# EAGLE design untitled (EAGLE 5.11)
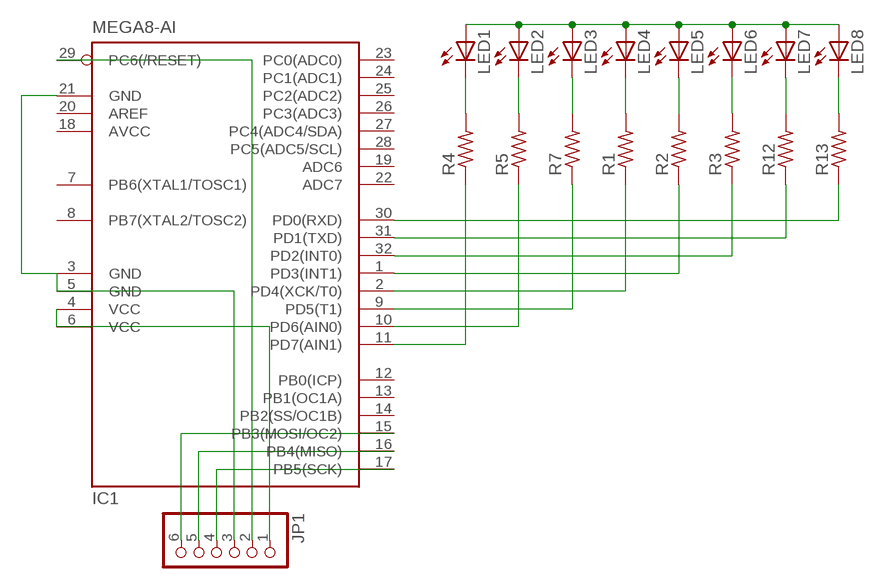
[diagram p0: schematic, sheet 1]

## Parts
IC1  MEGA8-AI  [TQFP32-08]
JP1  PINHD-1X6  [1X06]
LED1  LED3MM  [LED3MM]
LED2  LED3MM  [LED3MM]
LED3  LED3MM  [LED3MM]
LED4  LED3MM  [LED3MM]
LED5  LED3MM  [LED3MM]
LED6  LED3MM  [LED3MM]
LED7  LED3MM  [LED3MM]
LED8  LED3MM  [LED3MM]
R1  R-US_0207/2V  [0207/2V]
R2  R-US_0207/2V  [0207/2V]
R3  R-US_0207/2V  [0207/2V]
R4  R-US_0207/5V  [0207/5V]
R5  R-US_0207/5V  [0207/5V]
R7  R-US_0207/2V  [0207/2V]
R12  R-US_0207/2V  [0207/2V]
R13  R-US_0207/2V  [0207/2V]

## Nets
N$1: LED1.A LED2.A LED3.A LED4.A LED5.A LED6.A LED7.A LED8.A
N$2: IC1.11(PD7(AIN1)) R4.1
N$3: IC1.10(PD6(AIN0)) R5.1
N$4: IC1.9(PD5(T1)) R7.1
N$5: IC1.2(PD4(XCK/T0)) R1.1
N$6: IC1.1(PD3(INT1)) R2.1
N$7: IC1.32(PD2(INT0)) R3.1
N$8: IC1.31(PD1(TXD)) R12.1
N$9: IC1.30(PD0(RXD)) R13.1
N$14: IC1.15(PB3(MOSI/OC2)) JP1.6
N$15: IC1.16(PB4(MISO)) JP1.5
N$16: IC1.17(PB5(SCK)) JP1.4
N$17: IC1.29(PC6(/RESET)) JP1.2
N$18: IC1.4(VCC) IC1.6(VCC) JP1.1
N$22: IC1.3(GND) IC1.5(GND) IC1.21(GND) JP1.3
N$25: LED8.K(C) R13.2
N$28: LED7.K(C) R12.2
N$39: LED6.K(C) R3.2
N$40: LED5.K(C) R2.2
N$41: LED4.K(C) R1.2
N$42: LED3.K(C) R7.2
N$43: LED2.K(C) R5.2
N$44: LED1.K(C) R4.2
Unconnected: IC1.7(PB6(XTAL1/TOSC1)) IC1.8(PB7(XTAL2/TOSC2)) IC1.12(PB0(ICP)) IC1.13(PB1(OC1A)) IC1.14(PB2(SS/OC1B)) IC1.19(ADC6) IC1.20(AREF) IC1.22(ADC7) IC1.23(PC0(ADC0)) IC1.24(PC1(ADC1)) IC1.25(PC2(ADC2)) IC1.26(PC3(ADC3)) IC1.27(PC4(ADC4/SDA)) IC1.28(PC5(ADC5/SCL))

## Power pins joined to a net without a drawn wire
AVCC: IC1.18(AVCC)

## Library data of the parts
IC1 = atmel:MEGA8: MICROCONTROLLER 8 Kbytes FLASH, 1 kbytes SRAM, 512 bytes EEPROM, USART, 6-channel 10 bit ADC, 2-channel 8 bit ADC Pin compatible with Atmega48, ATMega88, ATMega168 Source: avr.lbr; MPN: ATMEGA8-16AU; OC_FARNELL: 9171371; OC_NEWARK: 73M8863
JP1 = pinhead:PINHD-1X6: PIN HEADER
LED1-LED8 = led:LED: LED
R1-R5 R7 R12 R13 = rcl:R-US_: RESISTOR, American symbol

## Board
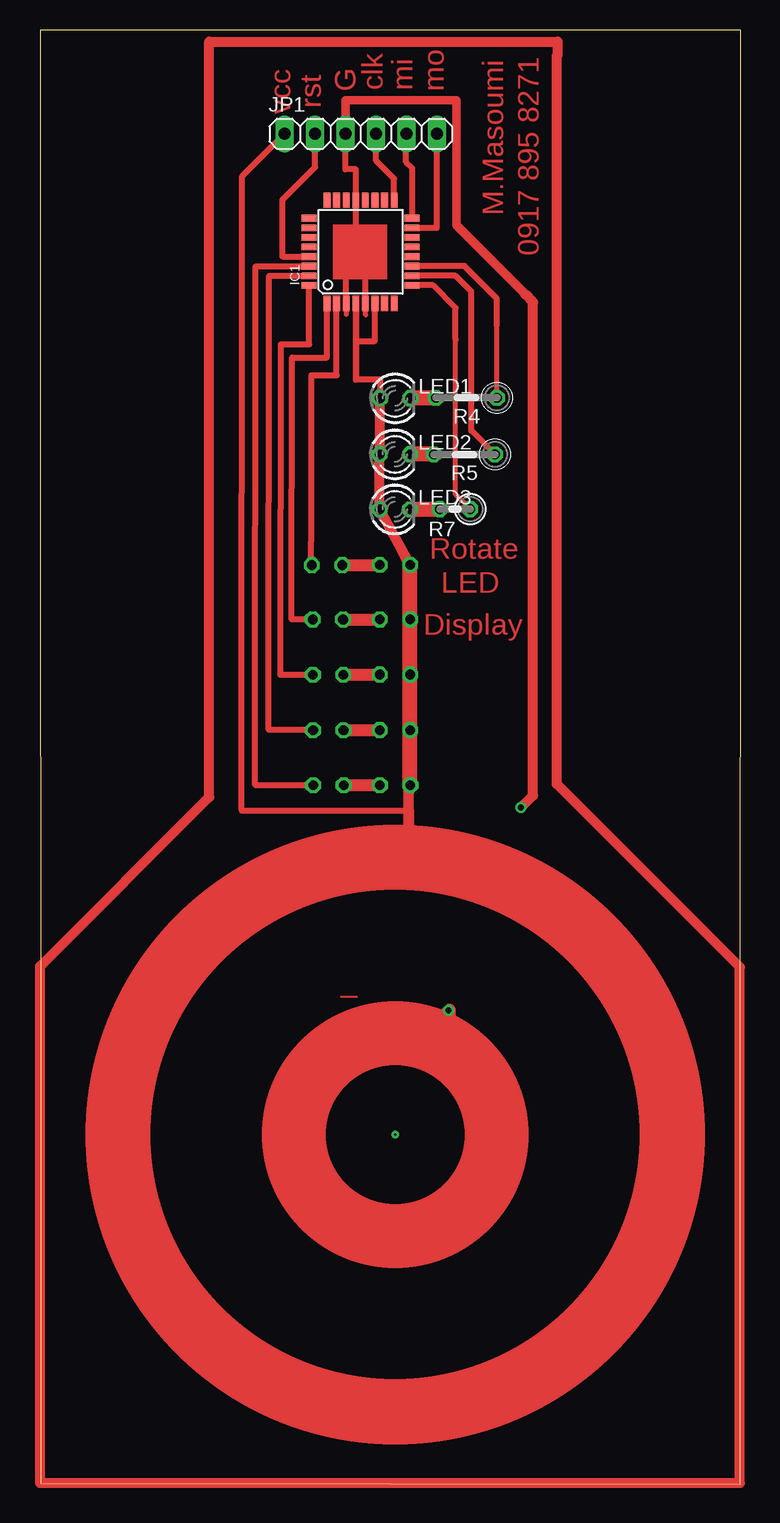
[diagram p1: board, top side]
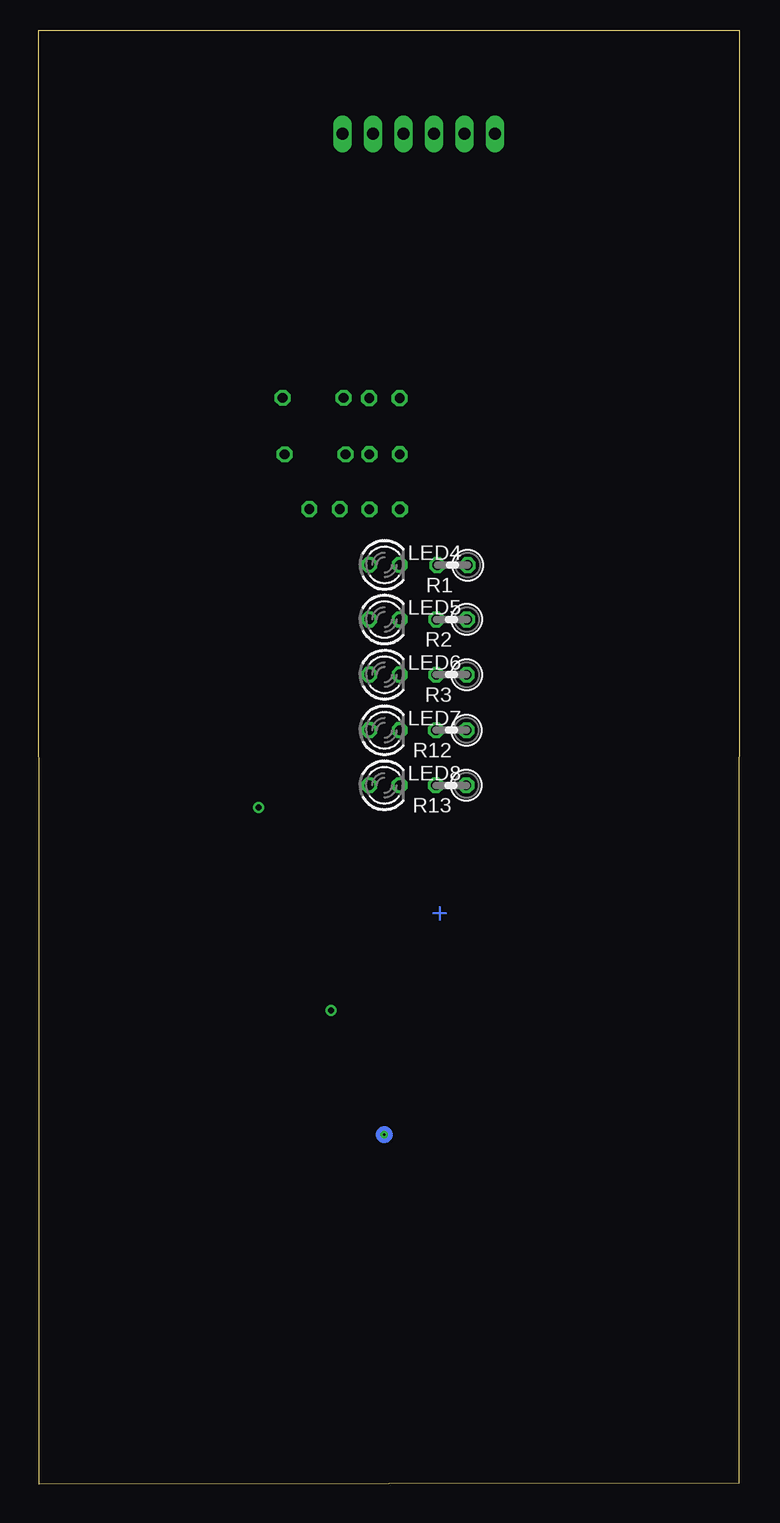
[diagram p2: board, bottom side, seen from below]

Size 58.41 x 121.22 mm. Coordinates in mm from the lower left corner, seen from the top.
Outline: 0.05,0.07 58.39,0 58.41,121.18 0,121.22 0.05,0.07
Copper layers (1*16): Top 0.035mm / dielectric 1.5mm / Bottom 0.035mm
Design rules "default": minimum track width 10mil, minimum drill 24mil, track to track 8mil, track to pad 8mil, pad to pad 8mil, via to via 8mil, smd to smd 8mil, copper to edge 40mil, drill to drill 8mil, minimum pad ring 10mil, minimum via ring 8mil, stop-mask expansion 4mil, vias tented up to drill 0mil, thermal gap 10mil

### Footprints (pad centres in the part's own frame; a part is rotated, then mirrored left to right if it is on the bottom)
TQFP32-08 = smd 1.27 x 0.559: 1 -4.293,2.8; 2 -4.293,2; 3 -4.293,1.2; 4 -4.293,0.4; 5 -4.293,-0.4; 6 -4.293,-1.2; 7 -4.293,-2; 8 -4.293,-2.8; 17 4.293,-2.8; 18 4.293,-2; 19 4.293,-1.2; 20 4.293,-0.4; 21 4.293,0.4; 22 4.293,1.2; 23 4.293,2; 24 4.293,2.8 | smd 0.559 x 1.27: 9 -2.8,-4.293; 10 -2,-4.293; 11 -1.2,-4.293; 12 -0.4,-4.293; 13 0.4,-4.293; 14 1.2,-4.293; 15 2,-4.293; 16 2.8,-4.293; 25 2.8,4.293; 26 2,4.293; 27 1.2,4.293; 28 0.4,4.293; 29 -0.4,4.293; 30 -1.2,4.293; 31 -2,4.293; 32 -2.8,4.293
1X06 = drill 1.016 long: 1 -6.35,0; 2 -3.81,0; 3 -1.27,0; 4 1.27,0; 5 3.81,0; 6 6.35,0
LED3MM = drill 0.813 octagon: A -1.27,0; K 1.27,0
0207/2V = drill 0.813 octagon: 1 -1.27,0; 2 1.27,0
0207/5V = drill 0.813 octagon: 1 -2.54,0; 2 2.54,0

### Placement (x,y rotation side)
IC1  26.73,102.73 90 top
JP1  26.74,112.57 0 top
LED1  29.61,90.53 0 top
LED2  29.59,85.86 0 top
LED3  29.59,81.27 0 top
LED4  29.59,76.64 0 bottom
LED5  29.6,72.09 0 bottom
LED6  29.6,67.49 0 bottom
LED7  29.6,62.86 0 bottom
LED8  29.6,58.27 0 bottom
R1  23.93,76.61 180 bottom
R2  24,72.09 180 bottom
R3  24.02,67.48 180 bottom
R4  35.55,90.56 180 top
R5  35.38,85.85 180 top
R7  34.6,81.29 180 top
R12  24.03,62.85 180 bottom
R13  24.05,58.26 180 bottom

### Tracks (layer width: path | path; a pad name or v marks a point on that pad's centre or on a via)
N$1
  Top 0.813: LED1.A 28.34,85.87 LED2.A LED3.A LED4.A
  Top 1.27: LED8.A LED7.A | LED7.A | LED7.A LED6.A LED5.A LED4.A
N$2
  Top 0.406: R4.1 38.09,96.6
  Top 0.483: IC1.11 35.39,101.54 38.09,98.84 38.09,96.6
N$3
  Top 0.483: IC1.10 34.64,100.73 35.96,99.42 35.96,95.9 35.96,95.49 35.96,87.81 R5.1
N$4
  Top 0.406: R7.1 34.66,82.5 34.66,95.44
  Top 0.483: IC1.9 31.03,99.94 32.76,99.94 34.66,98.05 34.66,95.44
N$5
  Top 0.483: R1.1 22.62,76.61 22.62,78.63 22.62,92.45 24.73,92.45 IC1.2
N$6
  Top 0.483: IC1.1 23.93,93.93 21.03,93.93 20.99,72.09 R2.1
N$7
  Top 0.483: IC1.32 22.44,95.02 20.09,95.02 20.05,67.48 R3.1
N$8
  Top 0.483: IC1.31 19.1,100.73 19.06,62.89 22.76,62.89 R12.1
N$9
  Top 0.483: IC1.30 17.98,101.53 17.93,58.29 22.78,58.29 R13.1
N$11
  Top 0.813: 30.73,54.23 30.73,58.88 31,58.88
N$12
  Top 0.813: 0.01,0.13 0.01,43.17 14.11,57.27 14.11,120.25 43.16,120.25 43.16,119.14 43.11,119.14
N$13  (via drill 0.23 pad 0.25)
  other vias: 29.61,29.15
N$14
  Top 0.483: JP1.6 33.09,104.73 IC1.15
N$15
  Top 0.483: IC1.16 31.05,105.53 31.05,109.69 30.52,110.22 30.52,112.53 JP1.5
N$16
  Top 0.483: IC1.17 29.53,108.82 28.02,110.33 JP1.4
N$17
  Top 0.483: IC1.29 20.2,102.33 20.2,107.07 22.93,109.8 JP1.2
N$18
  Top 0.483: IC1.6 27.93,95.3 26.33,95.3 | 26.33,95.3 IC1.4 26.33,92.08 | JP1.1 16.86,109.04 16.82,56.15 16.82,56.16 30.95,56.16 | 30.95,56.16 30.95,54.38 30.67,54.38 | 30.95,56.16 30.95,59.08 30.87,75.98 28.44,80.93 28.24,89.3 28.37,89.3 28.37,92.06 26.33,92.06 26.33,95.3
N$19
  Top 0.813: -0.03,0.1 58.35,0.1 58.35,43.12 43.1,58.37 43.1,119.07
N$22
  Top 0.483: IC1.3 25.53,102.09 26.33,102.09 | IC1.5 27.1,98.44 27.1,102.09 26.33,102.09 | 26.33,102.09 IC1.21 26.33,109.61 25.46,109.61 25.46,112.57 JP1.3
N$24
  Top 0.713: 25.48,111.88 25.48,115.37 34.7,115.37 34.7,104.94 40.45,99.19 | 40.11,56.39 40.45,56.73
  Top 0.813: 40.45,99.19 41.12,98.52 41.12,57.39 40.11,56.39
N$25
  Top 1.016: LED8.K 25.33,58.27 R13.2
N$28
  Top 1.016: R12.2 LED7.K
N$29  (via drill 0.5 pad 0.18)
  other vias: 40.1,56.42
N$30  (via drill 0.5 pad 0.18)
  other vias: 34.06,39.49
N$31
  Bottom 1.422: 29.61,29.15
N$32
  Top 0.713: 33.68,38.58 33.68,39.31 34.09,39.72 34.17,39.72 34.32,39.57 34.32,39.05 34,38.72
N$33
  Top 0.406: 25.54,97.52 25.54,98.28
N$34
  Top 0.406: 27.14,97.47 27.14,98.12
N$39
  Top 1.016: R3.2 28.31,67.48 LED6.K
N$40
  Top 1.016: R2.2 LED5.K
N$41
  Top 1.016: R1.2 28.29,76.61 LED4.K
N$42
  Top 1.27: LED3.K 30.88,81.29 R7.2
N$43
  Top 1.27: R5.2 LED2.K
N$44
  Top 1.27: LED1.K 30.91,90.56 R4.2
(copper drawn outside any net)
  shapes: Top area x1, Top circle x5

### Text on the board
Top: G | clk | mi | mo | rst | vcc | M.Masoumi | 0917 895 8271 | Rotate | LED | Display | _
Bottom: +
